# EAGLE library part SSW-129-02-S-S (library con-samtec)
THROUGH-HOLE .025" SQ POST SOCKET Source: Samtec SSW.pdf
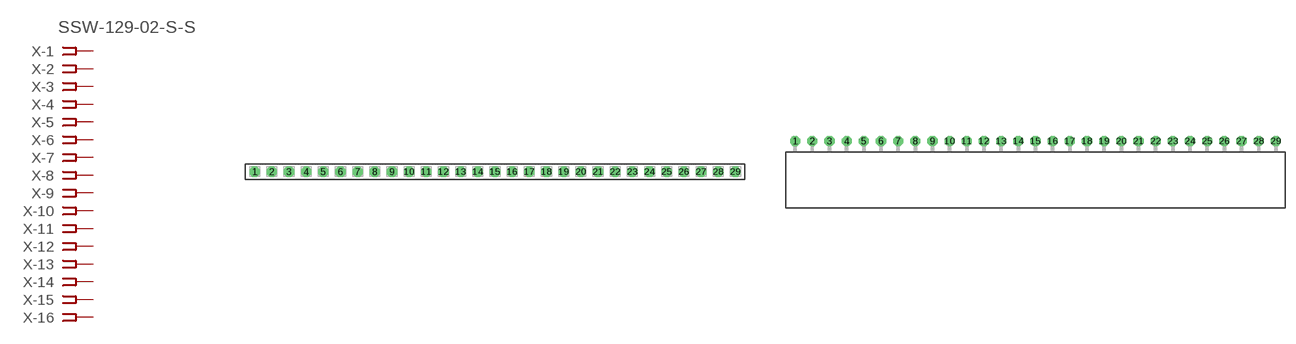
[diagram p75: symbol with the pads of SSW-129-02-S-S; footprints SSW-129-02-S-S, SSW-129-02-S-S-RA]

Designator prefix X; gates -1=FPINV -2=FPIN -3=FPIN -4=FPIN -5=FPIN -6=FPIN -7=FPIN -8=FPIN -9=FPIN -10=FPIN -11=FPIN -12=FPIN -13=FPIN -14=FPIN -15=FPIN -16=FPIN -17=FPIN -18=FPIN -19=FPIN -20=FPIN -21=FPIN -22=FPIN -23=FPIN -24=FPIN -25=FPIN -26=FPIN -27=FPIN -28=FPIN -29=FPIN

## SSW-129-02-S-S (MPN: SSW-129-02-S-S; OC_FARNELL: unknown; OC_NEWARK: 11P9791)  [SSW-129-02-S-S]
1  -1:1  pas
2  -2:1  pas
3  -3:1  pas
4  -4:1  pas
5  -5:1  pas
6  -6:1  pas
7  -7:1  pas
8  -8:1  pas
9  -9:1  pas
10  -10:1  pas
11  -11:1  pas
12  -12:1  pas
13  -13:1  pas
14  -14:1  pas
15  -15:1  pas
16  -16:1  pas
17  -17:1  pas
18  -18:1  pas
19  -19:1  pas
20  -20:1  pas
21  -21:1  pas
22  -22:1  pas
23  -23:1  pas
24  -24:1  pas
25  -25:1  pas
26  -26:1  pas
27  -27:1  pas
28  -28:1  pas
29  -29:1  pas

## SSW-129-02-S-S-RA (MPN: SSW-129-02-S-S-RA; OC_FARNELL: unknown; OC_NEWARK: 11P9792)  [SSW-129-02-S-S-RA]
Pads as for SSW-129-02-S-S

## Footprint SSW-129-02-S-S (pad centres in mm)
THROUGH-HOLE .025" SQ POST SOCKET Source: Samtec SSW.pdf
drill 1 pad 1.5 octagon: 1 -35.56,0; 2 -33.02,0; 3 -30.48,0; 4 -27.94,0; 5 -25.4,0; 6 -22.86,0; 7 -20.32,0; 8 -17.78,0; 9 -15.24,0; 10 -12.7,0; 11 -10.16,0; 12 -7.62,0; 13 -5.08,0; 14 -2.54,0; 15 0,0; 16 2.54,0; 17 5.08,0; 18 7.62,0; 19 10.16,0; 20 12.7,0; 21 15.24,0; 22 17.78,0; 23 20.32,0; 24 22.86,0; 25 25.4,0; 26 27.94,0; 27 30.48,0; 28 33.02,0; 29 35.56,0

## Footprint SSW-129-02-S-S-RA (pad centres in mm)
THROUGH-HOLE .025" SQ POST SOCKET Source: Samtec SSW.pdf
drill 1 pad 1.5 octagon: 1 -35.56,1.524; 2 -33.02,1.524; 3 -30.48,1.524; 4 -27.94,1.524; 5 -25.4,1.524; 6 -22.86,1.524; 7 -20.32,1.524; 8 -17.78,1.524; 9 -15.24,1.524; 10 -12.7,1.524; 11 -10.16,1.524; 12 -7.62,1.524; 13 -5.08,1.524; 14 -2.54,1.524; 15 0,1.524; 16 2.54,1.524; 17 5.08,1.524; 18 7.62,1.524; 19 10.16,1.524; 20 12.7,1.524; 21 15.24,1.524; 22 17.78,1.524; 23 20.32,1.524; 24 22.86,1.524; 25 25.4,1.524; 26 27.94,1.524; 27 30.48,1.524; 28 33.02,1.524; 29 35.56,1.524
